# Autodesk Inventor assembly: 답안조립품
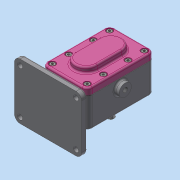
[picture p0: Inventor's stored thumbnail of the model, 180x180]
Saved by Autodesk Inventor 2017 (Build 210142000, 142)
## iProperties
Part Number: 답안조립품
Material: 일반
Document SubType Name: Assembly
Designer: MRC
Author: MRC
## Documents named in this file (11)
- C:\Users\MRC\Desktop\700407V1050\답안조립품.iam
- C:\Users\MRC\Desktop\700407V1050\본체.ipt
- C:\Users\MRC\Desktop\700407V1050\Ű 6 x 6 x 18.ipt
- C:\Users\MRC\Desktop\700407V1050\개스킷.ipt
- C:\Users\MRC\Desktop\700407V1050\메인축.ipt
- C:\Users\MRC\Desktop\700407V1050\베어링부시.ipt
- C:\Users\MRC\Desktop\700407V1050\볼트 M5.ipt
- C:\Users\MRC\Desktop\700407V1050\서브축.ipt
- C:\Users\MRC\Desktop\700407V1050\스퍼기어.ipt
- C:\Users\MRC\Desktop\700407V1050\오일 실 16 28 7.ipt
- C:\Users\MRC\Desktop\700407V1050\커버.ipt
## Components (3 placed, 2 different names)
1. Ű 6 x 6 x 18:1
2. 개스킷:1
3. Ű 6 x 6 x 18:2
